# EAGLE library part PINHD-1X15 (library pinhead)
PIN HEADER
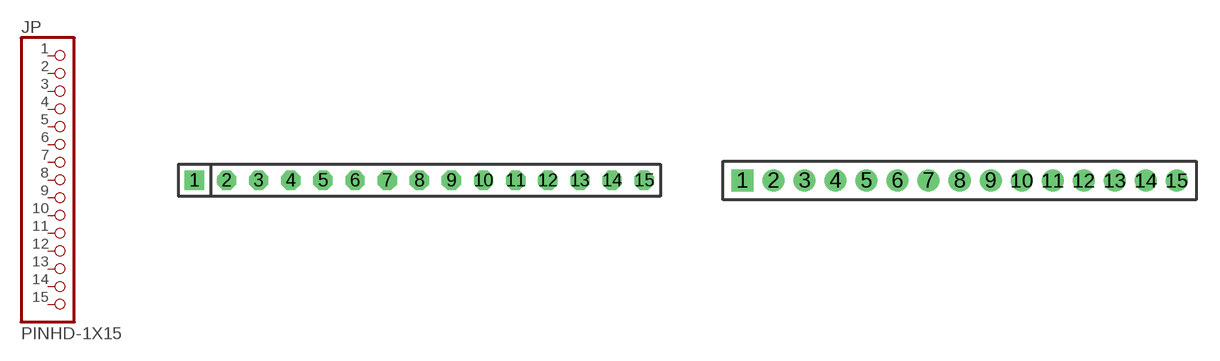
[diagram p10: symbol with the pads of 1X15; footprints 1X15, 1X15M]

Designator prefix JP

## PINHD-1X15  [1X15]
1  1  pas
2  2  pas
3  3  pas
4  4  pas
5  5  pas
6  6  pas
7  7  pas
8  8  pas
9  9  pas
10  10  pas
11  11  pas
12  12  pas
13  13  pas
14  14  pas
15  15  pas

## PINHD-1X15M  [1X15M]
Pads as for 1X15

## Footprint 1X15 (pad centres in mm)
PIN HEADER - 0.1"
drill 1.016 square: 1 -17.78,0
drill 1.016 octagon: 2 -15.24,0; 3 -12.7,0; 4 -10.16,0; 5 -7.62,0; 6 -5.08,0; 7 -2.54,0; 8 0,0; 9 2.54,0; 10 5.08,0; 11 7.62,0; 12 10.16,0; 13 12.7,0; 14 15.24,0; 15 17.78,0

## Footprint 1X15M (pad centres in mm)
PIN HEADER - 2MM"
drill 0.914 square: 1 -14,0
drill 0.914 round: 2 -12,0; 3 -10,0; 4 -8,0; 5 -6,0; 6 -4,0; 7 -2,0; 8 0,0; 9 2,0; 10 4,0; 11 6,0; 12 8,0; 13 10,0; 14 12,0; 15 14,0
